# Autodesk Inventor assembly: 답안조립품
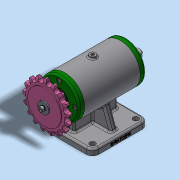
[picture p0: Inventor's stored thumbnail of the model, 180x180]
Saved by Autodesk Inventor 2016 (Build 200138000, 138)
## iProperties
Created: 2019-06
Part Number: 답안조립품
Material: 일반
Document SubType Name: Weldment
Designer: Administrator
Weld Material: Welded Aluminum-6061
Author: Administrator
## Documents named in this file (11)
- C:\Users\Administrator\Desktop\490604V1005\답안조립품.iam
- C:\Users\Administrator\Desktop\490604V1005\본체.ipt
- C:\Users\Administrator\Desktop\490604V1005\베어링 6203.ipt
- C:\Users\Administrator\Desktop\490604V1005\축.ipt
- C:\Users\Administrator\Desktop\490604V1005\커버.ipt
- C:\Users\Administrator\Desktop\490604V1005\오일 실 17 30 5.ipt
- C:\Users\Administrator\Desktop\490604V1005\볼트 M4.ipt
- C:\Users\Administrator\Desktop\490604V1005\키 4x4x12.ipt
- C:\Users\Administrator\Desktop\490604V1005\스프로킷.ipt
- C:\Users\Administrator\Desktop\490604V1005\평와셔.ipt
- C:\Users\Administrator\Desktop\490604V1005\스프링와셔.ipt
